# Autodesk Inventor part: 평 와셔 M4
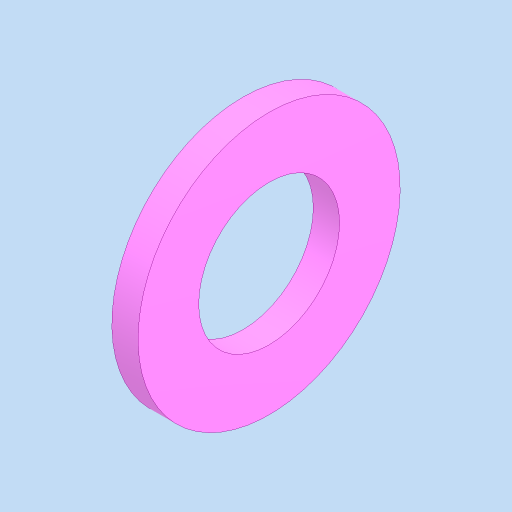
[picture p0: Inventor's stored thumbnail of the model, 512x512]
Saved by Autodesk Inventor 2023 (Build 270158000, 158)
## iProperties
Created: 2026-03
Part Number: 평 와셔 M4
Material: 강철, 연강
Description: 평면 와셔
Document SubType Name: Modeling
Designer: home
Density: 7.85 g/cm^3
Appearance: 기본값
Author: jhkim
Sending System: Autodesk Inventor 2026
Preprocessor: ST-DEVELOPER v20.1
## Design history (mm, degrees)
feature "Solid1"
node "솔리드1"
